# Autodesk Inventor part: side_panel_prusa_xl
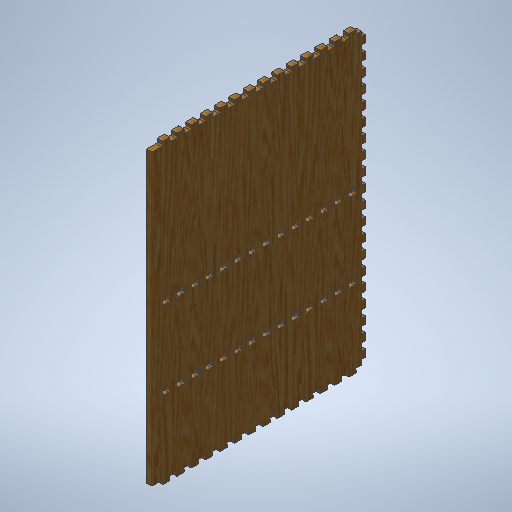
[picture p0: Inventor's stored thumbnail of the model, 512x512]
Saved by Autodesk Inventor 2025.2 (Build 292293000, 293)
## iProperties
Created: 2024-11
Part Number: side_panel_prusa_xl
Material: Plywood, Finish
Document SubType Name: Modeling
Designer: BennF
Density: 0.552 g/cm^3
Appearance: Plywood - New
Author: BennF
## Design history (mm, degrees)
sketch "Sketch2"
  geometry: L1 (-351, 484.5)-(351, 484.5); L2 (351, 484.5)-(351, -484.5); L3 (351, -484.5)-(-351, -484.5); L4 (-351, -484.5)-(-351, 484.5); 3 further points
  constraints: 8 end point, 2 midpoint, 2 parallel, 1 horizontal, 1 horizontal alignment, 1 perpendicular, 1 vertical alignment
  dimensions: "d0" = 702 distance of L1.start L1.end (= prusa_xl_depth - finger_depth); "d1" = 969 distance of L3.end L1.start (= prusa_xl_height - 2 x finger_depth)
extrude "base_material" new body sketch "Sketch2" distance "d2" = 18 (= thickness); taper "d3" = 0 deg
sketch "Sketch3"
  geometry: L1 (-484.5, -314.9)-(-498, -314.9); L2 (-498, -314.9)-(-498, -291.1); L3 (-498, -291.1)-(-484.5, -291.1); L4 (0, -351)-(0, 351); L5 (-467.9, 351)-(-467.9, 364.5); L6 (-467.9, 364.5)-(-444.1, 364.5); L7 (-444.1, 364.5)-(-444.1, 351); L8 (-484.5, -266.9)-(-498, -266.9); L9 (-498, -266.9)-(-498, -243.1); L10 (-498, -243.1)-(-484.5, -243.1); L11 (-484.5, -218.9)-(-498, -218.9); L12 (-498, -218.9)-(-498, -195.1); L13 (-498, -195.1)-(-484.5, -195.1); L14 (-484.5, -170.9)-(-498, -170.9); L15 (-498, -170.9)-(-498, -147.1); L16 (-498, -147.1)-(-484.5, -147.1); L17 (-484.5, -122.9)-(-498, -122.9); L18 (-498, -122.9)-(-498, -99.1); L19 (-498, -99.1)-(-484.5, -99.1); L20 (-484.5, -74.9)-(-498, -74.9); L21 (-498, -74.9)-(-498, -51.1); L22 (-498, -51.1)-(-484.5, -51.1); L23 (-484.5, -26.9)-(-498, -26.9); L24 (-498, -26.9)-(-498, -3.1); L25 (-498, -3.1)-(-484.5, -3.1); L26 (-484.5, 21.1)-(-498, 21.1); L27 (-498, 21.1)-(-498, 44.9); L28 (-498, 44.9)-(-484.5, 44.9); L29 (-484.5, 69.1)-(-498, 69.1); L30 (-498, 69.1)-(-498, 92.9); L31 (-498, 92.9)-(-484.5, 92.9); L32 (-484.5, 117.1)-(-498, 117.1); L33 (-498, 117.1)-(-498, 140.9); L34 (-498, 140.9)-(-484.5, 140.9); L35 (-484.5, 165.1)-(-498, 165.1); L36 (-498, 165.1)-(-498, 188.9); L37 (-498, 188.9)-(-484.5, 188.9); L38 (-484.5, 213.1)-(-498, 213.1); L39 (-498, 213.1)-(-498, 236.9); L40 (-498, 236.9)-(-484.5, 236.9); L41 (-484.5, 261.1)-(-498, 261.1); L42 (-498, 261.1)-(-498, 284.9); L43 (-498, 284.9)-(-484.5, 284.9); L44 (-484.5, 309.1)-(-498, 309.1); L45 (-498, 309.1)-(-498, 332.9); L46 (-498, 332.9)-(-484.5, 332.9); L47 (498, 236.9)-(484.5, 236.9); L48 (484.5, 213.1)-(498, 213.1); L49 (498, 213.1)-(498, 236.9); L50 (498, 188.9)-(484.5, 188.9); L51 (484.5, 165.1)-(498, 165.1); L52 (498, 165.1)-(498, 188.9); L53 (484.5, 261.1)-(498, 261.1); L54 (498, 261.1)-(498, 284.9); L55 (498, 284.9)-(484.5, 284.9); L56 (484.5, 309.1)-(498, 309.1); L57 (498, 309.1)-(498, 332.9); L58 (498, 332.9)-(484.5, 332.9); L59 (484.5, -170.9)-(498, -170.9); L60 (498, -170.9)-(498, -147.1); L61 (498, -147.1)-(484.5, -147.1); L62 (484.5, -122.9)-(498, -122.9); L63 (498, -122.9)-(498, -99.1); L64 (498, -99.1)-(484.5, -99.1)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; 103 further points
  constraints: 290 end point, 76 horizontal alignment, 64 parallel, 59 symmetric about line, 52 vertical alignment, 32 collinear, 4 perpendicular, 1 horizontal, 1 midpoint, 1 vertical, 13 other
  dimensions: "d4" = 23.8 distance of L1.end L2.end (derived); "d13" = 23.8 distance of L5.end L6.end (derived); "d22" = 13.5 distance of L1.start L1.end (derived); "d23" = 13.5 distance of L5.start L5.end (derived); "d26" = 48 distance of L1.start L8.start (= finger_distance); "d33" = 48 distance of L5.start L91.start (= finger_distance); "d40" = 36.1 distance between parallel lines of L90 L1 (derived); "d41" = 30.1 distance between parallel lines of L5 L45 (derived)
extrude "joints_1" join sketch "Sketch3" distance "d38" = 18 (= thickness); taper "d39" = 0 deg
sketch "Sketch5"
  geometry: L1 (-40.167, -315)-(-22.167, -315); L2 (-22.167, -315)-(-22.167, -291); L3 (-22.167, -291)-(-40.167, -291); L4 (-40.167, -291)-(-40.167, -315); L5 (-484.5, -314.9)-(-484.5, -351) reference; L6 (222.167, -315)-(240.167, -315); L7 (240.167, -315)-(240.167, -291); L8 (240.167, -291)-(222.167, -291); L9 (222.167, -291)-(222.167, -315); L10 (-40.167, -267)-(-22.167, -267); L11 (-40.167, -243)-(-40.167, -267); L12 (-22.167, -243)-(-40.167, -243); L13 (-22.167, -267)-(-22.167, -243); L14 (222.167, -243)-(222.167, -267); L15 (222.167, -267)-(240.167, -267); L16 (240.167, -267)-(240.167, -243); L17 (240.167, -243)-(222.167, -243); L18 (-40.167, -219)-(-22.167, -219); L19 (-40.167, -195)-(-40.167, -219); L20 (-22.167, -195)-(-40.167, -195); L21 (-22.167, -219)-(-22.167, -195); L22 (222.167, -195)-(222.167, -219); L23 (222.167, -219)-(240.167, -219); L24 (240.167, -219)-(240.167, -195); L25 (240.167, -195)-(222.167, -195); L26 (-40.167, -171)-(-22.167, -171); L27 (-40.167, -147)-(-40.167, -171); L28 (-22.167, -147)-(-40.167, -147); L29 (-22.167, -171)-(-22.167, -147); L30 (222.167, -147)-(222.167, -171); L31 (222.167, -171)-(240.167, -171); L32 (240.167, -171)-(240.167, -147); L33 (240.167, -147)-(222.167, -147); L34 (-40.167, -123)-(-22.167, -123); L35 (-40.167, -99)-(-40.167, -123); L36 (-22.167, -99)-(-40.167, -99); L37 (-22.167, -123)-(-22.167, -99); L38 (222.167, -99)-(222.167, -123); L39 (222.167, -123)-(240.167, -123); L40 (240.167, -123)-(240.167, -99); L41 (240.167, -99)-(222.167, -99); L42 (-40.167, -75)-(-22.167, -75); L43 (-40.167, -51)-(-40.167, -75); L44 (-22.167, -51)-(-40.167, -51); L45 (-22.167, -75)-(-22.167, -51); L46 (222.167, -51)-(222.167, -75); L47 (222.167, -75)-(240.167, -75); L48 (240.167, -75)-(240.167, -51); L49 (240.167, -51)-(222.167, -51); L50 (-40.167, -27)-(-22.167, -27); L51 (-40.167, -3)-(-40.167, -27); L52 (-22.167, -3)-(-40.167, -3); L53 (-22.167, -27)-(-22.167, -3); L54 (222.167, -3)-(222.167, -27); L55 (222.167, -27)-(240.167, -27); L56 (240.167, -27)-(240.167, -3); L57 (240.167, -3)-(222.167, -3); L58 (-40.167, 21)-(-22.167, 21); L59 (-40.167, 45)-(-40.167, 21); L60 (-22.167, 45)-(-40.167, 45); L61 (-22.167, 21)-(-22.167, 45); L62 (222.167, 45)-(222.167, 21); L63 (222.167, 21)-(240.167, 21); L64 (240.167, 21)-(240.167, 45)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; 1 further point
  constraints: 224 end point, 4 parallel, 2 equal length, 2 horizontal, 2 perpendicular, 1 collinear, 1 horizontal alignment, 1 vertical, 207 other
  dimensions: "d59" = 24 distance of L3.end L1.start (= finger_width); "d60" = 18 distance of L1.start L1.end (derived); "d61" = 444.33333 distance between parallel lines of L5 L4 (= box_clearence_1 + box_height_1); "d62" = 244.33333 distance from line of L8.end L2 (= box_clearence_1 + box_height_2); "d65" = 48 distance of L1.start L10.start (= finger_distance); "d70" = 36 distance between parallel lines of L1 L114 (derived)
  node "Sketch Rectangular Pattern7" dims "d65" = 48 (= finger_distance), "d68" = 10
extrude "joints_2" cut sketch "Sketch5" distance "d71" = 13.5 (derived); taper "d72" = 0 deg
sketch "Sketch4" dims "d42" = 6 (= dogbone_diameter)
  geometry: L1 (484.5, -351)-(484.5, -314.9) reference; L2 (484.5, -314.9)-(498, -314.9) reference; L3 (498, -314.9)-(498, -291.1) reference; L4 (498, -291.1)-(484.5, -291.1) reference; L5 (484.5, -291.1)-(484.5, -266.9) reference; L6 (484.5, -266.9)-(498, -266.9) reference; L7 (498, -266.9)-(498, -243.1) reference; L8 (498, -243.1)-(484.5, -243.1) reference; L9 (484.5, -243.1)-(484.5, -218.9) reference; L10 (484.5, -218.9)-(498, -218.9) reference; L11 (498, -218.9)-(498, -195.1) reference; L12 (498, -195.1)-(484.5, -195.1) reference; L13 (484.5, -195.1)-(484.5, -170.9) reference; L14 (484.5, -170.9)-(498, -170.9) reference; L15 (498, -170.9)-(498, -147.1) reference; L16 (498, -147.1)-(484.5, -147.1) reference; L17 (484.5, -147.1)-(484.5, -122.9) reference; L18 (484.5, -122.9)-(498, -122.9) reference; L19 (498, -122.9)-(498, -99.1) reference; L20 (498, -99.1)-(484.5, -99.1) reference; L21 (484.5, -99.1)-(484.5, -74.9) reference; L22 (484.5, -74.9)-(498, -74.9) reference; L23 (498, -74.9)-(498, -51.1) reference; L24 (498, -51.1)-(484.5, -51.1) reference; L25 (484.5, -51.1)-(484.5, -26.9) reference; L26 (484.5, -26.9)-(498, -26.9) reference; L27 (498, -26.9)-(498, -3.1) reference; L28 (498, -3.1)-(484.5, -3.1) reference; L29 (484.5, -3.1)-(484.5, 21.1) reference; L30 (484.5, 21.1)-(498, 21.1) reference; L31 (498, 21.1)-(498, 44.9) reference; L32 (498, 44.9)-(484.5, 44.9) reference; L33 (484.5, 44.9)-(484.5, 69.1) reference; L34 (484.5, 69.1)-(498, 69.1) reference; L35 (498, 69.1)-(498, 92.9) reference; L36 (498, 92.9)-(484.5, 92.9) reference; L37 (484.5, 92.9)-(484.5, 117.1) reference; L38 (484.5, 117.1)-(498, 117.1) reference; L39 (498, 117.1)-(498, 140.9) reference; L40 (498, 140.9)-(484.5, 140.9) reference; L41 (484.5, 140.9)-(484.5, 165.1) reference; L42 (484.5, 165.1)-(498, 165.1) reference; L43 (498, 165.1)-(498, 188.9) reference; L44 (498, 188.9)-(484.5, 188.9) reference; L45 (484.5, 188.9)-(484.5, 213.1) reference; L46 (484.5, 213.1)-(498, 213.1) reference; L47 (498, 213.1)-(498, 236.9) reference; L48 (498, 236.9)-(484.5, 236.9) reference; L49 (484.5, 236.9)-(484.5, 261.1) reference; L50 (484.5, 261.1)-(498, 261.1) reference; L51 (498, 261.1)-(498, 284.9) reference; L52 (498, 284.9)-(484.5, 284.9) reference; L53 (484.5, 284.9)-(484.5, 309.1) reference; L54 (484.5, 309.1)-(498, 309.1) reference; L55 (498, 309.1)-(498, 332.9) reference; L56 (498, 332.9)-(484.5, 332.9) reference; L57 (484.5, 332.9)-(484.5, 351) reference; L58 (484.5, 351)-(467.9, 351) reference; L59 (467.9, 351)-(467.9, 364.5) reference; L60 (467.9, 364.5)-(444.1, 364.5) reference; L61 (444.1, 364.5)-(444.1, 351) reference; L62 (444.1, 351)-(419.9, 351) reference; L63 (419.9, 351)-(419.9, 364.5) reference; L64 (419.9, 364.5)-(396.1, 364.5) reference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; 258 further points
  constraints: 204 end point, 134 symmetric about line, 56 vertical, 40 horizontal, 30 point on line, 6 midpoint, 4 perpendicular, 2 collinear, 2 horizontal alignment, 2 vertical alignment, 598 other
  dimensions: "d45" = 48 distance of L190.end L202.end (= finger_distance); "d52" = 48 distance of point (-441.979, 353.121) point (-393.979, 353.121) (= finger_distance)
extrude "dogbones_1" cut sketch "Sketch4" distance "d57" = 18 (= thickness); taper "d58" = 0 deg
sketch "Sketch6" dims "d80" = 6 (derived)
  geometry: L1 (-488.743, -195.1)-(-498, -195.1) reference; L2 (-498, -195.1)-(-498, -218.9) reference; L3 (-498, -218.9)-(-488.743, -218.9) reference; L4 (-484.5, -223.143)-(-484.5, -238.857) reference; L5 (-488.743, -243.1)-(-498, -243.1) reference; L6 (-498, -243.1)-(-498, -266.9) reference; L7 (-498, -266.9)-(-488.743, -266.9) reference; L8 (-484.5, -271.143)-(-484.5, -286.857) reference; L9 (-488.743, -291.1)-(-498, -291.1) reference; L10 (-498, -291.1)-(-498, -314.9) reference; L11 (-498, -314.9)-(-488.743, -314.9) reference; L12 (-484.5, -319.143)-(-484.5, -351) reference; L13 (-484.5, -351)-(484.5, -351) reference; L14 (484.5, -351)-(484.5, -319.143) reference; L15 (488.743, -314.9)-(498, -314.9) reference; L16 (498, -314.9)-(498, -291.1) reference; L17 (498, -291.1)-(488.743, -291.1) reference; L18 (484.5, -286.857)-(484.5, -271.143) reference; L19 (488.743, -266.9)-(498, -266.9) reference; L20 (498, -266.9)-(498, -243.1) reference; L21 (498, -243.1)-(488.743, -243.1) reference; L22 (484.5, -238.857)-(484.5, -223.143) reference; L23 (488.743, -218.9)-(498, -218.9) reference; L24 (498, -218.9)-(498, -195.1) reference; L25 (498, -195.1)-(488.743, -195.1) reference; L26 (484.5, -190.857)-(484.5, -175.143) reference; L27 (488.743, -170.9)-(498, -170.9) reference; L28 (498, -170.9)-(498, -147.1) reference; L29 (498, -147.1)-(488.743, -147.1) reference; L30 (484.5, -142.857)-(484.5, -127.143) reference; L31 (488.743, -122.9)-(498, -122.9) reference; L32 (498, -122.9)-(498, -99.1) reference; L33 (498, -99.1)-(488.743, -99.1) reference; L34 (484.5, -94.857)-(484.5, -79.143) reference; L35 (488.743, -74.9)-(498, -74.9) reference; L36 (498, -74.9)-(498, -51.1) reference; L37 (498, -51.1)-(488.743, -51.1) reference; L38 (484.5, -46.857)-(484.5, -31.143) reference; L39 (488.743, -26.9)-(498, -26.9) reference; L40 (498, -26.9)-(498, -3.1) reference; L41 (498, -3.1)-(488.743, -3.1) reference; L42 (484.5, 1.143)-(484.5, 16.857) reference; L43 (488.743, 21.1)-(498, 21.1) reference; L44 (498, 21.1)-(498, 44.9) reference; L45 (498, 44.9)-(488.743, 44.9) reference; L46 (484.5, 49.143)-(484.5, 64.857) reference; L47 (488.743, 69.1)-(498, 69.1) reference; L48 (498, 69.1)-(498, 92.9) reference; L49 (498, 92.9)-(488.743, 92.9) reference; L50 (484.5, 97.143)-(484.5, 112.857) reference; L51 (488.743, 117.1)-(498, 117.1) reference; L52 (498, 117.1)-(498, 140.9) reference; L53 (498, 140.9)-(488.743, 140.9) reference; L54 (484.5, 145.143)-(484.5, 160.857) reference; L55 (488.743, 165.1)-(498, 165.1) reference; L56 (498, 165.1)-(498, 188.9) reference; L57 (498, 188.9)-(488.743, 188.9) reference; L58 (484.5, 193.143)-(484.5, 208.857) reference; L59 (488.743, 213.1)-(498, 213.1) reference; L60 (498, 213.1)-(498, 236.9) reference; L61 (498, 236.9)-(488.743, 236.9) reference; L62 (484.5, 241.143)-(484.5, 256.857) reference; L63 (488.743, 261.1)-(498, 261.1) reference; L64 (498, 261.1)-(498, 284.9) reference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; A1 r 3 centre (-486.621, -192.979) between (-488.743, -195.1) and (-484.5, -190.857) reference; A2 r 3 centre (-486.621, -221.021) between (-484.5, -223.143) and (-488.743, -218.9) reference; A3 r 3 centre (-486.621, -240.979) between (-488.743, -243.1) and (-484.5, -238.857) reference; A4 r 3 centre (-486.621, -269.021) between (-484.5, -271.143) and (-488.743, -266.9) reference; A5 r 3 centre (-486.621, -288.979) between (-488.743, -291.1) and (-484.5, -286.857) reference; A6 r 3 centre (-486.621, -317.021) between (-484.5, -319.143) and (-488.743, -314.9) reference; A7 r 3 centre (486.621, -317.021) between (488.743, -314.9) and (484.5, -319.143) reference; A8 r 3 centre (486.621, -288.979) between (484.5, -286.857) and (488.743, -291.1) reference; A9 r 3 centre (486.621, -269.021) between (488.743, -266.9) and (484.5, -271.143) reference; A10 r 3 centre (486.621, -240.979) between (484.5, -238.857) and (488.743, -243.1) reference; A11 r 3 centre (486.621, -221.021) between (488.743, -218.9) and (484.5, -223.143) reference; A12 r 3 centre (486.621, -192.979) between (484.5, -190.857) and (488.743, -195.1) reference; A13 r 3 centre (486.621, -173.021) between (488.743, -170.9) and (484.5, -175.143) reference; A14 r 3 centre (486.621, -144.979) between (484.5, -142.857) and (488.743, -147.1) reference; A15 r 3 centre (486.621, -125.021) between (488.743, -122.9) and (484.5, -127.143) reference; A16 r 3 centre (486.621, -96.979) between (484.5, -94.857) and (488.743, -99.1) reference; A17 r 3 centre (486.621, -77.021) between (488.743, -74.9) and (484.5, -79.143) reference; A18 r 3 centre (486.621, -48.979) between (484.5, -46.857) and (488.743, -51.1) reference; A19 r 3 centre (486.621, -29.021) between (488.743, -26.9) and (484.5, -31.143) reference; A20 r 3 centre (486.621, -0.979) between (484.5, 1.143) and (488.743, -3.1) reference; A21 r 3 centre (486.621, 18.979) between (488.743, 21.1) and (484.5, 16.857) reference; A22 r 3 centre (486.621, 47.021) between (484.5, 49.143) and (488.743, 44.9) reference; A23 r 3 centre (486.621, 66.979) between (488.743, 69.1) and (484.5, 64.857) reference; A24 r 3 centre (486.621, 95.021) between (484.5, 97.143) and (488.743, 92.9) reference; A25 r 3 centre (486.621, 114.979) between (488.743, 117.1) and (484.5, 112.857) reference; A26 r 3 centre (486.621, 143.021) between (484.5, 145.143) and (488.743, 140.9) reference; A27 r 3 centre (486.621, 162.979) between (488.743, 165.1) and (484.5, 160.857) reference; A28 r 3 centre (486.621, 191.021) between (484.5, 193.143) and (488.743, 188.9) reference; A29 r 3 centre (486.621, 210.979) between (488.743, 213.1) and (484.5, 208.857) reference; A30 r 3 centre (486.621, 239.021) between (484.5, 241.143) and (488.743, 236.9) reference; A31 r 3 centre (486.621, 258.979) between (488.743, 261.1) and (484.5, 256.857) reference; A32 r 3 centre (486.621, 287.021) between (484.5, 289.143) and (488.743, 284.9) reference; A33 r 3 centre (486.621, 306.979) between (488.743, 309.1) and (484.5, 304.857) reference; A34 r 3 centre (486.621, 335.021) between (484.5, 337.143) and (488.743, 332.9) reference; A35 r 3 centre (470.021, 353.121) between (467.9, 355.243) and (472.143, 351) reference; A36 r 3 centre (441.979, 353.121) between (439.857, 351) and (444.1, 355.243) reference; A37 r 3 centre (422.021, 353.121) between (419.9, 355.243) and (424.143, 351) reference; A38 r 3 centre (393.979, 353.121) between (391.857, 351) and (396.1, 355.243) reference; A39 r 3 centre (374.021, 353.121) between (371.9, 355.243) and (376.143, 351) reference; A40 r 3 centre (345.979, 353.121) between (343.857, 351) and (348.1, 355.243) reference; A41 r 3 centre (326.021, 353.121) between (323.9, 355.243) and (328.143, 351) reference; A42 r 3 centre (297.979, 353.121) between (295.857, 351) and (300.1, 355.243) reference; A43 r 3 centre (278.021, 353.121) between (275.9, 355.243) and (280.143, 351) reference; A44 r 3 centre (249.979, 353.121) between (247.857, 351) and (252.1, 355.243) reference; A45 r 3 centre (230.021, 353.121) between (227.9, 355.243) and (232.143, 351) reference; A46 r 3 centre (201.979, 353.121) between (199.857, 351) and (204.1, 355.243) reference; A47 r 3 centre (182.021, 353.121) between (179.9, 355.243) and (184.143, 351) reference; A48 r 3 centre (153.979, 353.121) between (151.857, 351) and (156.1, 355.243) reference; A49 r 3 centre (134.021, 353.121) between (131.9, 355.243) and (136.143, 351) reference; A50 r 3 centre (105.979, 353.121) between (103.857, 351) and (108.1, 355.243) reference; A51 r 3 centre (86.021, 353.121) between (83.9, 355.243) and (88.143, 351) reference; A52 r 3 centre (57.979, 353.121) between (55.857, 351) and (60.1, 355.243) reference; A53 r 3 centre (38.021, 353.121) between (35.9, 355.243) and (40.143, 351) reference; A54 r 3 centre (9.979, 353.121) between (7.857, 351) and (12.1, 355.243) reference; A55 r 3 centre (-9.979, 353.121) between (-12.1, 355.243) and (-7.857, 351) reference; A56 r 3 centre (-38.021, 353.121) between (-40.143, 351) and (-35.9, 355.243) reference; A57 r 3 centre (-57.979, 353.121) between (-60.1, 355.243) and (-55.857, 351) reference; A58 r 3 centre (-86.021, 353.121) between (-88.143, 351) and (-83.9, 355.243) reference; A59 r 3 centre (-105.979, 353.121) between (-108.1, 355.243) and (-103.857, 351) reference; A60 r 3 centre (-134.021, 353.121) between (-136.143, 351) and (-131.9, 355.243) reference; A61 r 3 centre (-153.979, 353.121) between (-156.1, 355.243) and (-151.857, 351) reference; A62 r 3 centre (-182.021, 353.121) between (-184.143, 351) and (-179.9, 355.243) reference; A63 r 3 centre (-201.979, 353.121) between (-204.1, 355.243) and (-199.857, 351) reference; A64 r 3 centre (-230.021, 353.121) between (-232.143, 351) and (-227.9, 355.243) reference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; 113 further points
  constraints: 112 end point, 112 point on line, 105 vertical, 596 other
  dimensions: "d83" = 48 distance of L277.start L314.end (derived)
extrude "dogbones_2" cut sketch "Sketch6" distance "d88" = 13.5 (derived); taper "d89" = 0 deg
body "Solid1"
node "Sketch Rectangular Pattern3" dims "d26" = 48 (= finger_distance), "d29" = 10
node "Projected Loop1"
node "Sketch Rectangular Pattern4" dims "d33" = 48 (= finger_distance), "d36" = 10
node "Projected Loop2"
node "Sketch Rectangular Pattern5" dims "d45" = 48 (= finger_distance), "d48" = 10
node "Sketch Rectangular Pattern6" dims "d52" = 48 (= finger_distance), "d55" = 10
node "Projected Loop4"
node "Sketch Rectangular Pattern9" dims "d83" = 48 (derived), "d86" = 10
other parameters: "thickness" = 18 [user parameter; used in 3 equation terms], "finger_depth" = 18 [user parameter; used in 2 equation terms], "finger_width" = 24 [user parameter; used in 1 equation term], "finger_distance" = 48 [user parameter; used in 5 equation terms], "prusa_xl_depth" = 720 [user parameter; used in 1 equation term], "dogbone_diameter" = 6 [user parameter; used in 1 equation term], "prusa_xl_height" = 1005 [user parameter; used in 1 equation term], "prusa_xl_height_finger_distance" = 34.5 [user parameter], "prusa_xl_depth_finger_distance" = 36 [user parameter], "mill_bit" = 6 [user parameter], "dogbone_angle" = 45 deg [user parameter], "prusa_xl_width_finger_distance" = 36 [user parameter], "prusa_xl_shelf_depth" = 702 [user parameter], "prusa_xl_shelf_width" = 684 [user parameter], "box_clearence_1" = 9.33333 [user parameter; used in 2 equation terms], "box_height_1" = 435 [user parameter; used in 1 equation term], "box_height_2" = 235 [user parameter; used in 1 equation term], "hidden_depth" = 4.5 [user parameter], "connection_clearence" = 0.2 [user parameter], "sla_width" = 1296 [user parameter], "back_distance" = 5 [user parameter], "back_connection_depth" = 5 [user parameter], "storage_width_2" = 322 [user parameter], "box_clearence_2" = 24.33333 [user parameter], "shelf_depth_finger_distance" = 39 [user parameter], "connection_back_clearence" = 0 [user parameter], "thickness_back" = 6 [user parameter], "finger_depth_middle" = 8 [user parameter], "box_height_3" = 285 [user parameter], "bowden_tube_diameter" = 4 [user parameter], "connector_width_offset" = 105 [user parameter], "connector_width" = 26 [user parameter], "connector_depth" = 16 [user parameter]
